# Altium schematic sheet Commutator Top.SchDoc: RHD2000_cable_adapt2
size 190 x 195 mm; Origin: Eagle; Date: 9/12/2022 12:10:57; SheetNumber: 1; GateName_1: G$1; SymbolName_1: LETTER_L; LibraryName: frames; DeviceSetName: LETTER_L; GateName_2: G$2; SymbolName_2: DOCFIELD; Sheet: Sheet:; REV: REV:
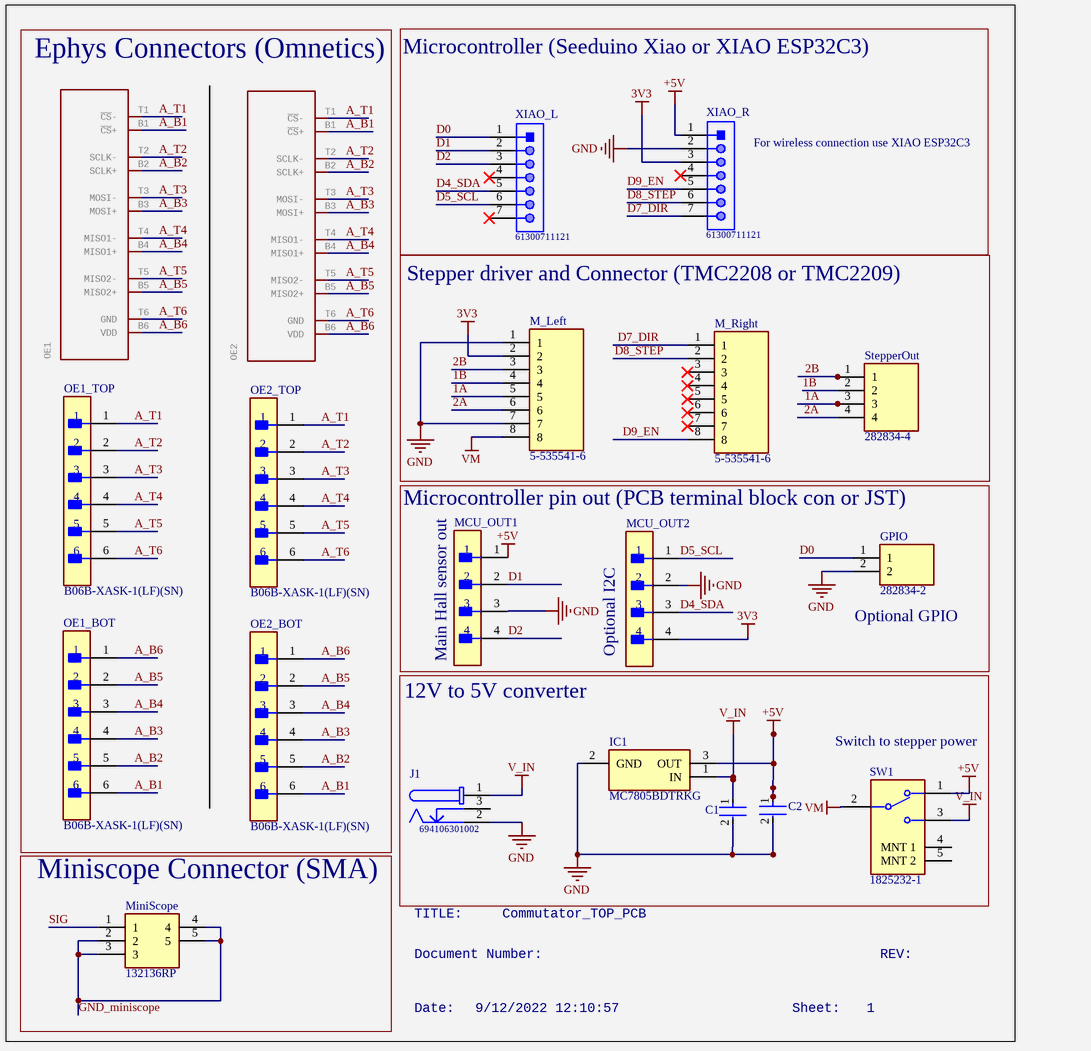
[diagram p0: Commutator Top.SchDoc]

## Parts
C1  (no value)  [FP-C1206C-EH-MFG]
C2  (no value)  [FP-C1206C-EH-MFG]
GPIO  282834-2  [282834-2_1]
IC1  MC7805BDTRKG  [LM317MADTRKG]
J1  694106301002  [694106301002]
M_Left  5-535541-6  [RHDR8W76P0X254_1X8_2032X356X673P]
M_Right  5-535541-6  [RHDR8W76P0X254_1X8_2032X356X673P]
MCU_OUT1  B04B-XASK-1(LF)(SN)  [FP-B04B-XASK-1_LF_SN-MFG]  (value not drawn)
MCU_OUT2  B04B-XASK-1(LF)(SN)  [FP-B04B-XASK-1_LF_SN-MFG]  (value not drawn)
MiniScope  132136RP  [132136RP]
OE1  RHD2000-CABLE-DAQ-SIDE  [RHD2000_EVAL_BOARD_OMNETICS_PZN-12-AA]  (value not drawn)
OE1_BOT  B06B-XASK-1(LF)(SN)  [FP-B06B-XASK-1_LF_SN-MFG]
OE1_TOP  B06B-XASK-1(LF)(SN)  [FP-B06B-XASK-1_LF_SN-MFG]
OE2  RHD2000-CABLE-DAQ-SIDE  [RHD2000_EVAL_BOARD_OMNETICS_PZN-12-AA]  (value not drawn)
OE2_BOT  B06B-XASK-1(LF)(SN)  [FP-B06B-XASK-1_LF_SN-MFG]
OE2_TOP  B06B-XASK-1(LF)(SN)  [FP-B06B-XASK-1_LF_SN-MFG]
StepperOut  282834-4  [2828344]
SW1  1825232-1  [FP-1825232-1-MFG]
XIAO_L  61300711121  [61300711121]
XIAO_R  61300711121  [61300711121]

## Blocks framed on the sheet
Ephys Connectors (Omnetics): OE1 OE1_BOT OE1_TOP OE2 OE2_BOT OE2_TOP
Microcontroller (Seeduino Xiao or XIAO ESP32C3): XIAO_L XIAO_R
Stepper driver and Connector (TMC2208 or TMC2209): M_Left M_Right StepperOut
Microcontroller pin out (PCB terminal block con or JST): GPIO MCU_OUT1 MCU_OUT2
12V to 5V converter: C1 C2 IC1 J1 SW1
Miniscope Connector (SMA): MiniScope

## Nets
3V3: M_Left.2 MCU_OUT2.4 XIAO_R.3
+5V: C2.1 IC1.3(OUT) MCU_OUT1.1 SW1.1 XIAO_R.1
GND: C1.2 C2.2 GPIO.2 IC1.2(GND) J1.2 M_Left.1 M_Left.7 MCU_OUT1.3 MCU_OUT2.2 XIAO_R.2
V_IN: C1.1 IC1.1(IN) J1.1 SW1.3
VM: M_Left.8 SW1.2
1A: M_Left.5 StepperOut.3
1B: M_Left.4 StepperOut.2
2A: M_Left.6 StepperOut.4
2B: M_Left.3 StepperOut.1
A_B1: OE1.B1(~{CS}+) OE1_BOT.6 OE2.B1(~{CS}+) OE2_BOT.6
A_B2: OE1.B2(SCLK+) OE1_BOT.5 OE2.B2(SCLK+) OE2_BOT.5
A_B3: OE1.B3(MOSI+) OE1_BOT.4 OE2.B3(MOSI+) OE2_BOT.4
A_B4: OE1.B4(MISO1+) OE1_BOT.3 OE2.B4(MISO1+) OE2_BOT.3
A_B5: OE1.B5(MISO2+) OE1_BOT.2 OE2.B5(MISO2+) OE2_BOT.2
A_B6: OE1.B6(VDD) OE1_BOT.1 OE2.B6(VDD) OE2_BOT.1
A_T1: OE1.T1(~{CS}-) OE1_TOP.1 OE2.T1(~{CS}-) OE2_TOP.1
A_T2: OE1.T2(SCLK-) OE1_TOP.2 OE2.T2(SCLK-) OE2_TOP.2
A_T3: OE1.T3(MOSI-) OE1_TOP.3 OE2.T3(MOSI-) OE2_TOP.3
A_T4: OE1.T4(MISO1-) OE1_TOP.4 OE2.T4(MISO1-) OE2_TOP.4
A_T5: OE1.T5(MISO2-) OE1_TOP.5 OE2.T5(MISO2-) OE2_TOP.5
A_T6: OE1.T6(GND) OE1_TOP.6 OE2.T6(GND) OE2_TOP.6
D0: GPIO.1 XIAO_L.1
D1: MCU_OUT1.2 XIAO_L.2
D2: MCU_OUT1.4 XIAO_L.3
D4_SDA: MCU_OUT2.3 XIAO_L.5
D5_SCL: MCU_OUT2.1 XIAO_L.6
D7_DIR: M_Right.1 XIAO_R.7
D8_STEP: M_Right.2 XIAO_R.6
D9_EN: M_Right.8 XIAO_R.5
GND_miniscope: MiniScope.2 MiniScope.3 MiniScope.4 MiniScope.5
SIG: MiniScope.1

Not connected (* = marked no-connect by the designer): J1 3; M_Right 3* 4* 5* 6* 7*; SW1 4(MNT_1) 5(MNT_2); XIAO_L 4* 7*; XIAO_R 4*

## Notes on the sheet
- (near XIAO_R) For wireless connection use XIAO ESP32C3
- (near MCU_OUT1) Main Hall sensor out
- (near MCU_OUT2) Optional I2C
- (near GPIO) Optional GPIO
- (near SW1) Switch to stepper power
- TITLE:
- Commutator_TOP_PCB
- Document Number:
- REV:
- Date:
- 9/12/2022 12:10:57
- Sheet:
- 1

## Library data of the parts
C1 C2 = CMP-1037-05005-3: CAP CER 100UF 6.3V X5R 1206; Dielectric Material: Ceramic; Tolerance: 2%; Dissipation Factor: 5%
GPIO = 282834-2: Connector; Manufacturer_Name: TE Connectivity
IC1 = MC7805BDTRKG: Integrated Circuit; Manufacturer_Name: onsemi
J1 = CMP-1502-00188-1: DC Power Jack Connector WR-DC, Male, Right Angled, THT, 5 A, 24 V; Manufacturer: Wurth Elektronik; Plug Inner Diameter: 2.05mm; Opening Diameter: 6.4mm; Rated Current: 5A; Plug Outer Diameter: 5.5mm; Working Voltage: 24V
M_Left M_Right = 5-535541-6: Connector; Manufacturer_Name: TE Connectivity
MCU_OUT1 MCU_OUT2 = CMP-17439-000018-1: CONN HEADER VERT 4POS 2.5MM; Manufacturer: JST; Current Rating: 3A; Voltage Rating: 250V; Conn Orientation: Straight; Conn Gender: Male; Number Of Contacts: 4
MiniScope = 132136RP: Connector; Manufacturer_Name: Amphenol
OE1 OE2 = RHD2000-CABLE-DAQ-SIDE: Omnetics PZN-12-AA RHD2000 socket - DAQ side; GateName_1: A
OE1_BOT OE1_TOP OE2_BOT OE2_TOP = CMP-17439-000268-1: CONN HEADER VERT 6POS 2.5MM; Voltage Rating: 250V; Contact Resistance: 20mR; Number of Poles: 6; Current Rating: 3A; Insulation Resistance: 1GR; Mated Stacking Heights: 11.3mm; Lead Length: 3.4mm; Gender: Male; Wire/Cable Gauge: 20AWG
StepperOut = 282834-4: Connector; Manufacturer_Name: TE Connectivity
SW1 = CMP-03405-000001-1: SWITCH SLIDE SPDT 200MA 30V; Manufacturer: TE Connectivity; Contact Current Rating: 0.2A; Contact Resistance: 20mΩ; Electromechanical Life: 10000Cycles; Operating Force: 200gf
XIAO_L XIAO_R = CMP-1502-01074-1: THT Vertical Pin Header WR-PHD, Pitch 2.54 mm, Single Row, 7 pins; Manufacturer: Wurth Elektronik; Pin Number: 7; Gender: Male; Working Voltage: 250VAC; Contact Resistance: 20mOhm; Rated Current: 3A; Pitch: 2.54mm; Withstanding Voltage: 500VAC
